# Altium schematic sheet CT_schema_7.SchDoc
size 280 x 236 mm
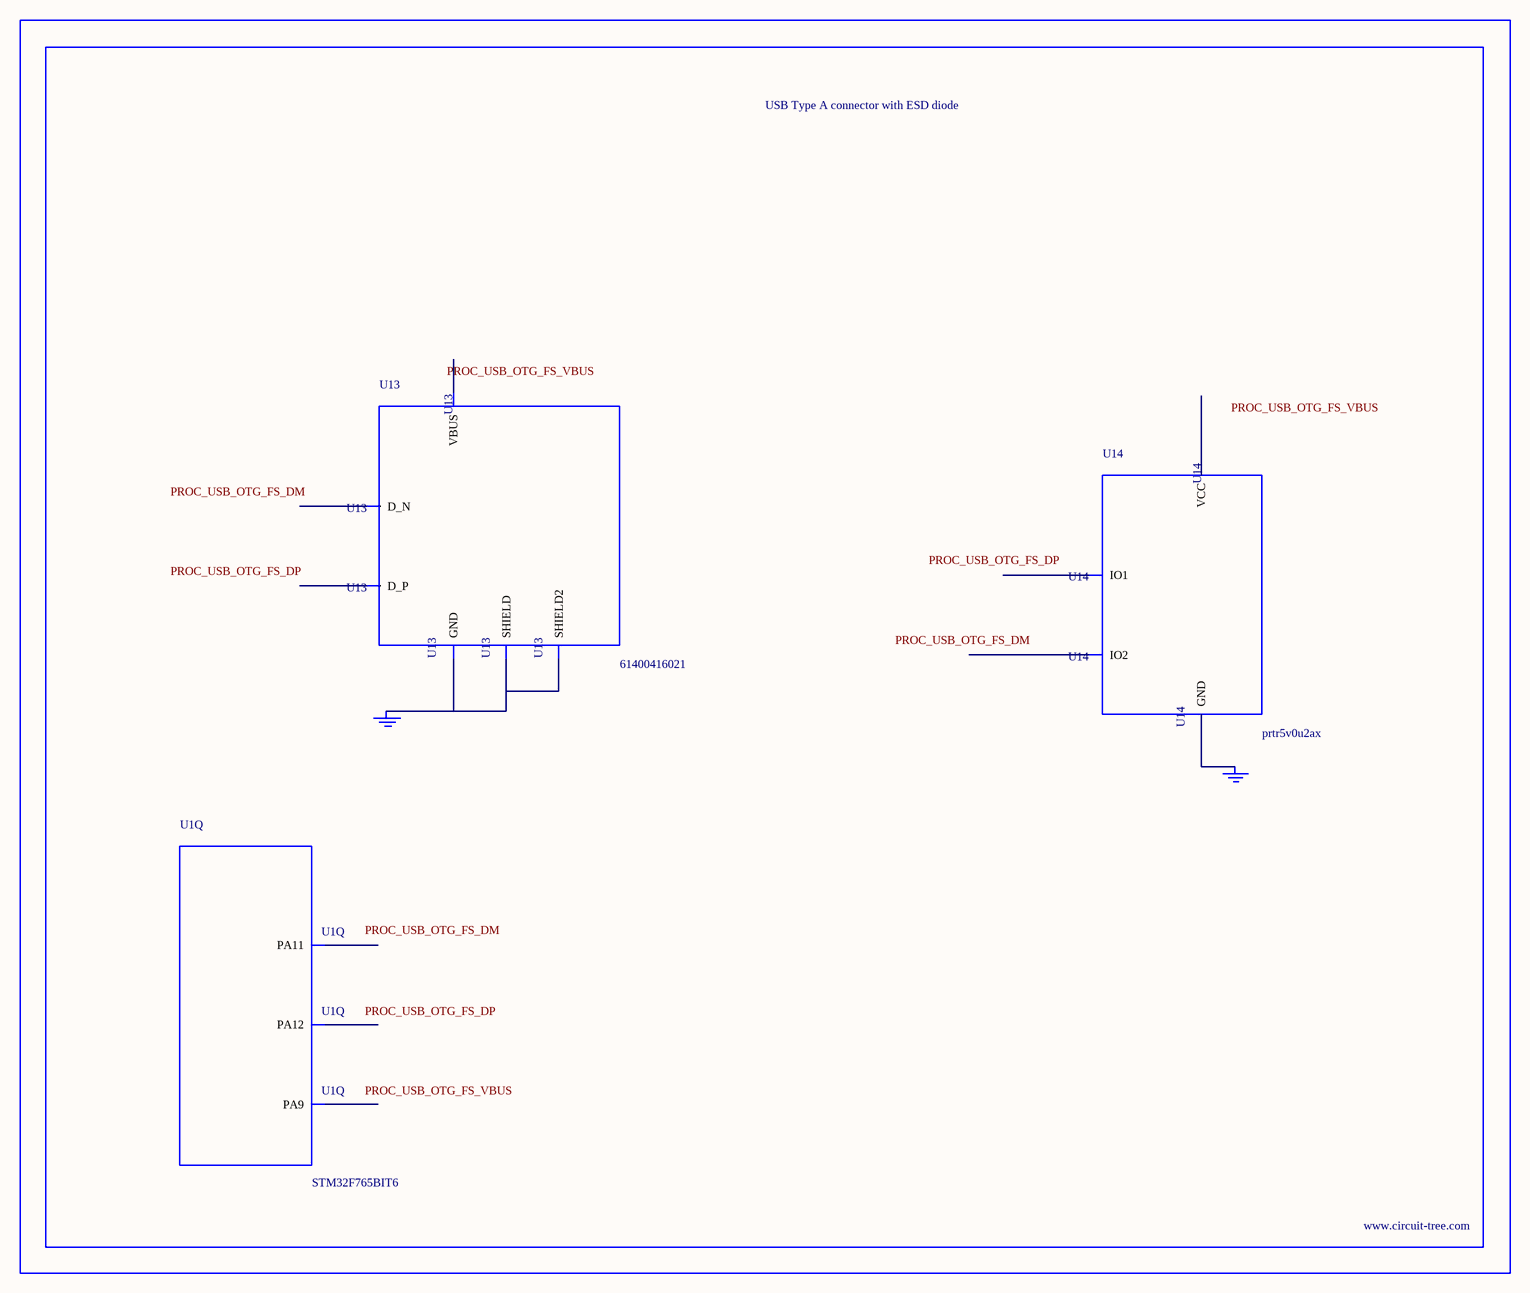
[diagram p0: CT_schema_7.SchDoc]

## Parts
BORDER6  (no value)
GND_INSTANCE_6_0  (no value)
GND_INSTANCE_6_1  (no value)
U1  STM32F765BIT6  [LQFP208]  (part Q of 17)
U13  61400416021  [USB-A-H]
U14  prtr5v0u2ax  [SOT143B]

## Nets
NetGND_INSTANCE_6_0_0: GND_INSTANCE_6_0.0(GND) U13.4(GND) U13.5(SHIELD) U13.6(SHIELD2)
NetGND_INSTANCE_6_1_0: GND_INSTANCE_6_1.0(GND) U14.1(GND)

Not connected (* = marked no-connect by the designer): U1 143(PA9) 145(PA11) 146(PA12); U13 1(VBUS) 2(D_N) 3(D_P); U14 2(IO1) 3(IO2) 4(VCC)

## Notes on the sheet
- Labels drawn without touching a wire or pin: PROC_USB_OTG_FS_DM, PROC_USB_OTG_FS_DP, PROC_USB_OTG_FS_VBUS

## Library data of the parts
BORDER6 = BORDER_PAGE6
GND_INSTANCE_6_0 GND_INSTANCE_6_1 = GND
